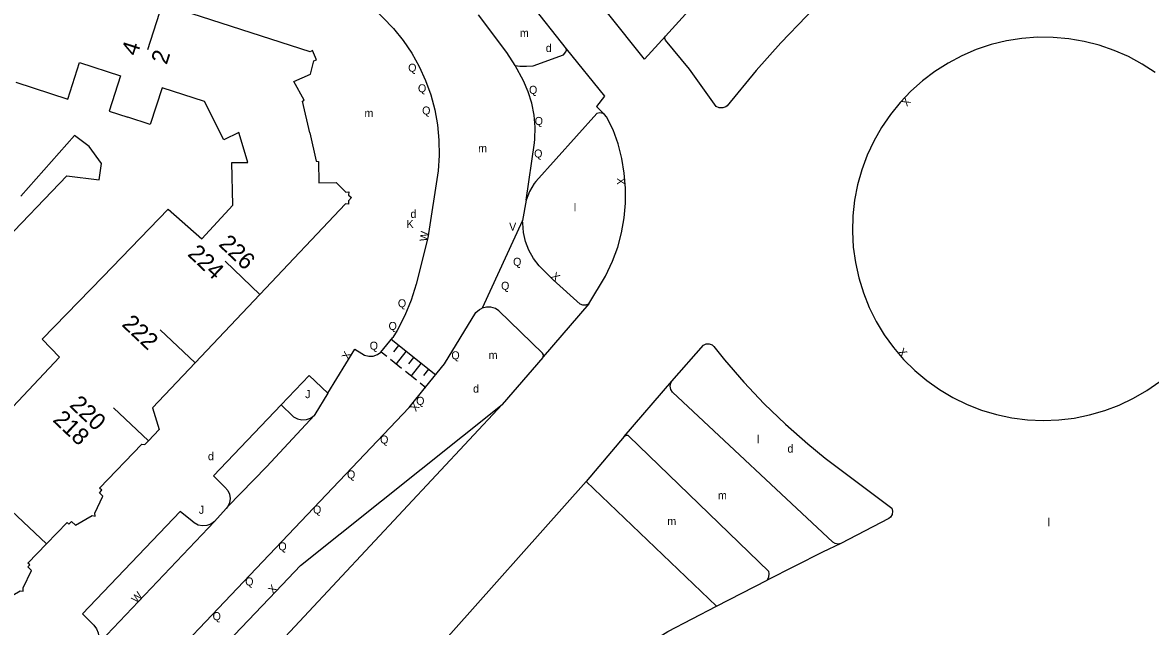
# Model space of a CAD drawing. Extents: x 134999 to 136502, y 457398 to 459002.
# Drawn here: x 135114.8 to 135185.3, y 457859.9 to 457897.6 of the extents above; entities that cross this region are included whole.
import ezdxf

# ---------------------------------------------------------------- set-up
doc = ezdxf.new("R2010")
doc.units = 0
for name, color, linetype in [('RI_DGTB_15', 7, 'Continuous'), ('RI_DGTB_29', 7, 'Continuous'), ('RI_DGTB_30', 7, 'Continuous'), ('RI_DGTB_31', 7, 'Continuous'), ('RI_DGTB_35', 7, 'Continuous'), ('RI_DGTB_36', 7, 'Continuous'), ('RI_DGTB_4', 7, 'Continuous'), ('RI_DGTB_43', 7, 'Continuous'), ('RI_DGTB_5', 7, 'Continuous'), ('RI_DGTB_53', 7, 'Continuous'), ('RI_DGTB_54', 7, 'Continuous')]:
    doc.layers.add(name, color=color, linetype=linetype)

msp = doc.modelspace()

# ---------------------------------------------------------------- linework, layer by layer
at = {"layer": 'RI_DGTB_15'}
for p, q in [((135123.505, 457898.732), (135122.587, 457895.877)), ((135129.605, 457880.605), (135127.428, 457882.669)), ((135125.554, 457876.329), (135123.377, 457878.393)), ((135122.638, 457871.452), (135120.461, 457873.516)), ((135116.269, 457865.022), (135114.092, 457867.086))]:
    msp.add_line(p, q, dxfattribs=at)
at = {"layer": 'RI_DGTB_31'}
for p, q in [((135140.605, 457875.552), (135137.802, 457877.775)), ((135137.529, 457876.713), (135137.178, 457876.993)), ((135138.267, 457877.41), (135137.955, 457877.019)), ((135138.735, 457877.039), (135138.114, 457876.253)), ((135138.463, 457875.971), (135137.763, 457876.531)), ((135139.201, 457876.665), (135138.895, 457876.271)), ((135139.672, 457876.292), (135139.049, 457875.507)), ((135139.4, 457875.234), (135138.698, 457875.793)), ((135140.137, 457875.923), (135139.823, 457875.533)), ((135139.984, 457874.77), (135139.63, 457875.047))]:
    msp.add_line(p, q, dxfattribs=at)
at = {"layer": 'RI_DGTB_4'}
msp.add_line((135129.605, 457880.605), (135125.554, 457876.329), dxfattribs=at)
for points in [[(135132.72, 457890.699), (135132.263, 457892.683), (135132.372, 457892.732), (135131.735, 457893.91), (135132.758, 457894.37), (135132.978, 457895.2), (135133.146, 457895.256), (135132.901, 457895.841), (135132.753, 457895.758), (135123.505, 457898.732)], [(135132.72, 457890.699), (135133.127, 457888.936), (135133.273, 457888.908), (135133.279, 457887.574), (135134.371, 457887.602), (135134.982, 457886.993), (135135.157, 457887.01), (135135.148, 457886.808), (135135.323, 457886.66), (135135.136, 457886.447), (135135.137, 457886.235), (135134.958, 457886.255), (135129.605, 457880.605)], [(135125.554, 457876.329), (135122.888, 457873.515), (135123.313, 457872.162), (135122.638, 457871.452)], [(135116.269, 457865.022), (135117.553, 457866.358), (135117.672, 457866.248), (135117.839, 457866.411), (135118.09, 457866.172), (135119.128, 457866.783), (135119.318, 457866.742), (135119.296, 457866.932), (135119.801, 457867.985), (135119.582, 457868.211), (135119.724, 457868.361), (135119.592, 457868.495), (135122.225, 457871.24), (135122.409, 457871.212), (135122.638, 457871.452)], [(135110.678, 457859.169), (135113.097, 457861.719), (135113.241, 457861.57), (135113.365, 457861.733), (135113.609, 457861.475), (135114.629, 457862.08), (135114.813, 457862.063), (135114.809, 457862.26), (135115.34, 457863.355), (135115.108, 457863.569), (135115.231, 457863.7), (135115.099, 457863.804), (135116.269, 457865.022)]]:
    msp.add_lwpolyline(points, dxfattribs=at)
at = {"layer": 'RI_DGTB_5'}
msp.add_line((135110.839, 457870.048), (135117.091, 457876.681), dxfattribs=at)
for points in [[(135114.347, 457893.866), (135117.597, 457892.807), (135118.33, 457895.102), (135120.896, 457894.264), (135120.191, 457892.054), (135121.35, 457891.675)], [(135128.557, 457889.82), (135128.295, 457890.716), (135127.361, 457890.251), (135126.153, 457892.649), (135123.492, 457893.519), (135122.757, 457891.215), (135121.35, 457891.675)], [(135125.981, 457884.071), (135127.921, 457886.181), (135127.851, 457888.841), (135128.843, 457888.845), (135128.557, 457889.82)], [(135119.783, 457881.708), (135123.871, 457885.931), (135125.981, 457884.071)], [(135119.783, 457881.708), (135116.011, 457877.811), (135117.091, 457876.681)]]:
    msp.add_lwpolyline(points, dxfattribs=at)
at = {"layer": 'RI_DGTB_53'}
for p, q in [((135146.472, 457898.812), (135148.736, 457895.957)), ((135146.236, 457886.484), (135146.024, 457885.23)), ((135146.024, 457885.23), (135143.486, 457879.739)), ((135150.15, 457880.007), (135147.314, 457876.698)), ((135147.284, 457876.659), (135144.748, 457873.716)), ((135147.314, 457876.698), (135147.284, 457876.659)), ((135152.372, 457871.722), (135155.353, 457875.184)), ((135152.372, 457871.722), (135149.995, 457868.912)), ((135158.139, 457861.123), (135149.995, 457868.912)), ((135127.489, 457867.225), (135126.76, 457866.42)), ((135127.581, 457867.328), (135127.489, 457867.225)), ((135158.139, 457861.123), (135161.301, 457862.74))]:
    msp.add_line(p, q, dxfattribs=at)
for points in [[(135164.746, 457907.324), (135169.854, 457904.005), (135169.914, 457903.878), (135169.93, 457903.687), (135169.868, 457903.505), (135169.737, 457903.365), (135168.876, 457902.663), (135167.106, 457901.159), (135165.4, 457899.605), (135163.75, 457897.992), (135162.156, 457896.324), (135160.621, 457894.601), (135158.795, 457892.384), (135158.721, 457892.331), (135158.522, 457892.257), (135158.309, 457892.262), (135158.113, 457892.344), (135156.458, 457894.685), (135154.942, 457896.485), (135154.896, 457896.633), (135154.946, 457896.747)], [(135154.946, 457896.747), (135164.506, 457907.279), (135164.619, 457907.34), (135164.746, 457907.324)], [(135117.076, 457906.629), (135134.895, 457899.663), (135135.489, 457899.401), (135136.047, 457899.068), (135136.233, 457898.934), (135137.287, 457897.912), (135137.949, 457897.218), (135138.552, 457896.471), (135139.09, 457895.677), (135139.56, 457894.841), (135139.958, 457893.969), (135140.283, 457893.066), (135140.531, 457892.139), (135140.702, 457891.195), (135140.793, 457890.24), (135140.804, 457889.281), (135140.735, 457888.324), (135140.105, 457884.13), (135139.379, 457881.238), (135139.053, 457880.246), (135138.652, 457879.281), (135138.179, 457878.35), (135137.922, 457877.909)], [(135145.547, 457894.916), (135145.03, 457895.719), (135143.266, 457898.079)], [(135154.946, 457896.747), (135153.647, 457895.308), (135151.32, 457898.193), (135151.088, 457898.543)], [(135185.555, 457894.459), (135184.735, 457894.993), (135183.875, 457895.459), (135182.98, 457895.853), (135182.055, 457896.172), (135181.108, 457896.415), (135180.143, 457896.58), (135179.169, 457896.665), (135178.191, 457896.671), (135177.216, 457896.596), (135176.25, 457896.442), (135175.299, 457896.21), (135174.371, 457895.901), (135173.472, 457895.517), (135172.606, 457895.061), (135171.781, 457894.536), (135171.002, 457893.945), (135170.273, 457893.292), (135169.618, 457892.603)], [(135145.547, 457894.916), (135145.854, 457894.871), (135146.266, 457894.864), (135146.676, 457894.879), (135148.567, 457895.579), (135148.731, 457895.765), (135148.768, 457895.866), (135148.736, 457895.957)], [(135148.736, 457895.957), (135151.145, 457892.995), (135150.63, 457892.338), (135151.148, 457891.85)], [(135146.236, 457886.484), (135146.757, 457890.071), (135146.779, 457890.309), (135146.797, 457891.059), (135146.734, 457891.807), (135146.593, 457892.544), (135146.373, 457893.262), (135146.079, 457893.953), (135145.547, 457894.916)], [(135169.618, 457892.603), (135169.001, 457891.844), (135168.449, 457891.036), (135167.964, 457890.187), (135167.551, 457889.3), (135167.211, 457888.383), (135166.947, 457887.441), (135166.761, 457886.481), (135166.654, 457885.508), (135166.627, 457884.531), (135166.68, 457883.554), (135166.812, 457882.585), (135167.023, 457881.629), (135167.312, 457880.695), (135167.675, 457879.787), (135168.112, 457878.911), (135168.619, 457878.075), (135169.193, 457877.282), (135169.829, 457876.539), (135170.524, 457875.851), (135171.272, 457875.221), (135172.07, 457874.655), (135172.911, 457874.156), (135173.791, 457873.727), (135174.702, 457873.372), (135175.639, 457873.092), (135176.596, 457872.889), (135177.567, 457872.766), (135178.544, 457872.722), (135179.521, 457872.758), (135180.493, 457872.874), (135181.451, 457873.068), (135182.391, 457873.341), (135183.305, 457873.689), (135184.187, 457874.111), (135185.033, 457874.603), (135185.835, 457875.163)], [(135151.148, 457891.85), (135151.046, 457891.911), (135150.855, 457891.952), (135150.663, 457891.913), (135146.84, 457887.666), (135146.746, 457887.532), (135146.455, 457887.025), (135146.236, 457886.484)], [(135150.15, 457880.007), (135151.206, 457881.739), (135151.644, 457882.678), (135151.961, 457883.556), (135152.202, 457884.459), (135152.365, 457885.379), (135152.448, 457886.31), (135152.452, 457887.244), (135152.376, 457888.175), (135152.22, 457889.096), (135151.986, 457890.001), (135151.676, 457890.882), (135151.272, 457891.706), (135151.148, 457891.85)], [(135150.15, 457880.007), (135149.974, 457879.929), (135149.782, 457879.928), (135149.626, 457879.991), (135147.941, 457881.516), (135147.047, 457882.383), (135146.699, 457882.852), (135146.418, 457883.364), (135146.21, 457883.909), (135146.078, 457884.478), (135146.025, 457885.06), (135146.024, 457885.23)], [(135139.952, 457874.795), (135141.139, 457876.265), (135143.105, 457879.464), (135143.319, 457879.651), (135143.486, 457879.739)], [(135147.314, 457876.698), (135147.329, 457876.823), (135147.271, 457876.933), (135144.528, 457879.577), (135144.317, 457879.714), (135144.046, 457879.801), (135143.762, 457879.809), (135143.486, 457879.739)], [(135137.171, 457877.001), (135137.922, 457877.909)], [(135155.353, 457875.184), (135157.314, 457877.43), (135157.49, 457877.512), (135157.683, 457877.517), (135157.863, 457877.443), (135157.963, 457877.353), (135158.629, 457876.504), (135159.846, 457875.109), (135161.123, 457873.769), (135162.456, 457872.485), (135163.843, 457871.259), (135164.93, 457870.37), (135169.095, 457867.251), (135169.144, 457867.053), (135169.114, 457866.851), (135169.009, 457866.676), (135168.911, 457866.591), (135165.914, 457865.038)], [(135133.855, 457874.422), (135135.542, 457877.189), (135135.975, 457876.905), (135136.151, 457876.808), (135136.417, 457876.74), (135136.69, 457876.751), (135136.949, 457876.841), (135137.171, 457877.001)], [(135133.855, 457874.422), (135132.694, 457875.535), (135130.93, 457873.693)], [(135108.198, 457838.197), (135111.566, 457844.632), (135111.844, 457844.995), (135112.108, 457845.28), (135112.273, 457845.489), (135138.942, 457873.543), (135139.952, 457874.795)], [(135165.914, 457865.038), (135165.729, 457864.994), (135165.542, 457865.029), (135165.4, 457865.122), (135155.392, 457874.489), (135155.28, 457874.661), (135155.242, 457874.862), (135155.283, 457875.063), (135155.353, 457875.184)], [(135133.855, 457874.422), (135133.047, 457873.097), (135132.995, 457873.041)], [(135110.462, 457837.057), (135112.424, 457840.803), (135114.916, 457845.6), (135121.984, 457852.991), (135130.592, 457862.031), (135132.137, 457863.66), (135144.748, 457873.716)], [(135130.93, 457873.693), (135126.715, 457869.263), (135127.425, 457868.562), (135127.602, 457868.357), (135127.712, 457868.109), (135127.745, 457867.84), (135127.699, 457867.574), (135127.581, 457867.328)], [(135130.93, 457873.693), (135131.66, 457872.994), (135131.714, 457872.95), (135131.959, 457872.816), (135132.232, 457872.756), (135132.51, 457872.776), (135132.772, 457872.874), (135132.995, 457873.041)], [(135127.581, 457867.328), (135130.042, 457869.85), (135132.995, 457873.041)], [(135161.301, 457862.74), (135161.406, 457862.934), (135161.435, 457863.152), (135161.413, 457863.288), (135152.664, 457871.737), (135152.607, 457871.775), (135152.483, 457871.788), (135152.372, 457871.722)], [(135084.993, 457800), (135134.123, 457851.567), (135140.34, 457858.07), (135149.995, 457868.912)], [(135126.76, 457866.42), (135126.542, 457866.252), (135126.285, 457866.153), (135126.011, 457866.131), (135125.741, 457866.189), (135125.5, 457866.321), (135125.37, 457866.44), (135124.63, 457867.03), (135118.52, 457860.64), (135119.22, 457859.93), (135119.398, 457859.713), (135119.508, 457859.455), (135119.541, 457859.177), (135119.494, 457858.9), (135119.372, 457858.648), (135119.25, 457858.5)], [(135165.914, 457865.038), (135164.77, 457864.489), (135161.301, 457862.74)], [(135138.101, 457845.546), (135140.422, 457847.89), (135142.181, 457849.623), (135143.996, 457851.298), (135145.863, 457852.913), (135147.782, 457854.467), (135149.751, 457855.958), (135151.766, 457857.384), (135153.827, 457858.744), (135155.097, 457859.536), (135158.139, 457861.123)]]:
    msp.add_lwpolyline(points, dxfattribs=at)
at = {"layer": 'RI_DGTB_54'}
for p, q in [((135110.462, 457837.057), (135144.748, 457873.716)), ((135119.25, 457858.5), (135126.76, 457866.42))]:
    msp.add_line(p, q, dxfattribs=at)
msp.add_lwpolyline([(135099.472, 457873.64), (135106.001, 457880.491), (135107.421, 457880.561), (135109.071, 457879.181), (135117.551, 457888.021), (135119.57, 457887.767), (135119.711, 457888.781), (135118.931, 457889.851), (135118.021, 457890.541), (135114.666, 457886.746)], dxfattribs=at)

# ---------------------------------------------------------------- texts
at = {"layer": 'RI_DGTB_29'}
for p in [(135147.469, 457895.752), (135139.015, 457885.382), (135142.924, 457874.464), (135162.57, 457870.717)]:
    msp.add_text('d', height=0.5, dxfattribs=at).set_placement(p)
msp.add_text('d', height=0.5, rotation=359.99965, dxfattribs=at).set_placement((135126.36, 457870.24))
msp.add_text('d', height=0.5, rotation=359.99965, dxfattribs=at).set_placement((135126.36, 457870.24))
msp.add_text('d', height=0.5, rotation=359.99965, dxfattribs=at).set_placement((135126.36, 457870.24))
at = {"layer": 'RI_DGTB_30'}
for s, rotation, p in [('X', 229.71483, (135169.934, 457892.966)), ('X', 90.89129, (135152.429, 457887.449)), ('W', 81.56442, (135140.069, 457883.882)), ('X', 317.8535, (135147.755, 457881.684)), ('X', 62.9532, (135135.134, 457876.484)), ('X', 310.1473, (135169.425, 457876.989)), ('X', 231.63792, (135139.223, 457873.895)), ('W', 47.81539, (135121.893, 457861.273)), ('W', 47.81539, (135121.893, 457861.273)), ('W', 47.81539, (135121.893, 457861.273)), ('X', 46.40301, (135130.42, 457861.85))]:
    msp.add_text(s, height=0.5, rotation=rotation, dxfattribs=at).set_placement(p)
for s, p in [('K', (135138.769, 457884.753)), ('V', (135145.18, 457884.588))]:
    msp.add_text(s, height=0.5, dxfattribs=at).set_placement(p)
at = {"layer": 'RI_DGTB_31'}
for s, p in [('Q', (135138.87, 457894.516)), ('Q', (135139.481, 457893.232)), ('Q', (135146.421, 457893.135)), ('Q', (135139.742, 457891.842)), ('Q', (135146.775, 457891.191)), ('Q', (135146.741, 457889.154)), ('Q', (135145.425, 457882.39)), ('Q', (135144.674, 457880.891)), ('Q', (135138.227, 457879.796)), ('Q', (135137.644, 457878.38)), ('Q', (135136.466, 457877.146)), ('Q', (135141.57, 457876.547)), ('J', (135132.434, 457874.118)), ('Q', (135139.369, 457873.7)), ('Q', (135137.116, 457871.28)), ('Q', (135135.046, 457869.099)), ('Q', (135132.924, 457866.904)), ('Q', (135130.759, 457864.606)), ('Q', (135128.687, 457862.41)), ('Q', (135126.651, 457860.244))]:
    msp.add_text(s, height=0.5, dxfattribs=at).set_placement(p)
msp.add_text('J', height=0.5, rotation=359.99965, dxfattribs=at).set_placement((135125.79, 457866.89))
msp.add_text('J', height=0.5, rotation=359.99965, dxfattribs=at).set_placement((135125.79, 457866.89))
msp.add_text('J', height=0.5, rotation=359.99965, dxfattribs=at).set_placement((135125.79, 457866.89))
at = {"layer": 'RI_DGTB_35'}
for s, rotation, p in [('2', 72.1799, (135123.78, 457894.914)), ('226', 316.5459, (135126.978, 457883.682))]:
    msp.add_text(s, height=1.054, rotation=rotation, dxfattribs=at).set_placement(p)
at = {"layer": 'RI_DGTB_36'}
for s, rotation, p in [('4', 72.1689, (135121.926, 457895.451)), ('224', 316.5538, (135125.036, 457883.065)), ('222', 316.5538, (135120.921, 457878.677)), ('220', 316.5538, (135117.652, 457873.629)), ('218', 316.5538, (135116.614, 457872.706))]:
    msp.add_text(s, height=1.054, rotation=rotation, dxfattribs=at).set_placement(p)
at = {"layer": 'RI_DGTB_43'}
msp.add_text('m', height=0.5, rotation=0.16348, dxfattribs=at).set_placement((135145.851, 457896.689))
for s, p in [('m', (135136.14, 457891.686)), ('m', (135143.243, 457889.488)), ('l', (135149.221, 457885.795)), ('m', (135143.898, 457876.563)), ('l', (135160.669, 457871.302)), ('m', (135158.227, 457867.796)), ('m', (135155.063, 457866.183)), ('l', (135178.822, 457866.114))]:
    msp.add_text(s, height=0.5, dxfattribs=at).set_placement(p)

doc.saveas('drawing.dxf')
